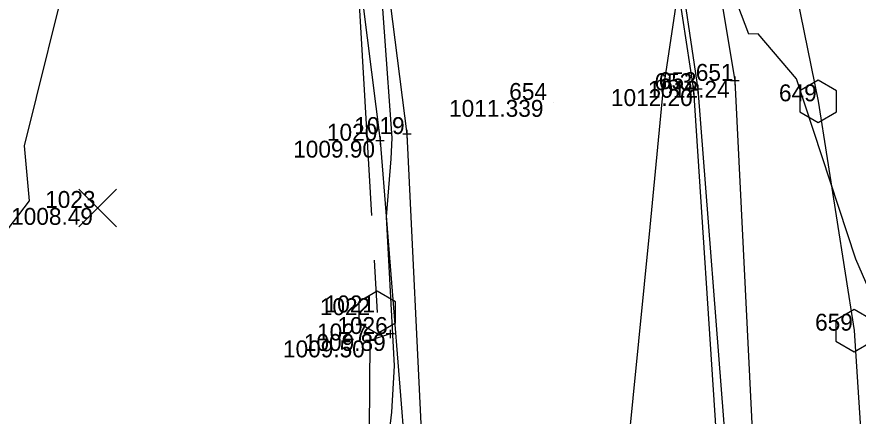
# Model space of a CAD drawing. Extents: x 2354693 to 2355622, y 637071 to 710080.
# Drawn here: x 2355324.2 to 2355383.9, y 709220.3 to 709248.7 of the extents above; entities that cross this region are included whole.
import ezdxf

# ---------------------------------------------------------------- set-up
doc = ezdxf.new("R2010")
doc.units = 0
for name, color, linetype in [('DT_X_Contour_Major', 7, 'Continuous'), ('DT_X_Contour_Minor', 7, 'Continuous'), ('PM_X_Surveyed_Line', 7, 'Continuous'), ('PV_X_EOP', 7, 'Continuous'), ('PV_X_Shoulder', 7, 'Continuous'), ('RD_X_Cells', 7, 'Continuous'), ('RD_X_GR_Lt', 7, 'Continuous'), ('RD_X_GR_Rt', 7, 'Continuous'), ('SV_X_Random_Point', 7, 'Continuous'), ('SV_X_Shot_Marker', 7, 'Continuous'), ('SV_X_Text_Elevation', 7, 'Continuous'), ('SV_X_Text_Name', 7, 'Continuous')]:
    doc.layers.add(name, color=color, linetype=linetype)

msp = doc.modelspace()

# ---------------------------------------------------------------- linework, layer by layer
at = {"layer": 'DT_X_Contour_Major'}
msp.add_lwpolyline([(2355382.151, 709274.282), (2355381.711, 709274.976), (2355380.703, 709275.914), (2355376.833, 709277.662), (2355375.801, 709278.001), (2355375.775, 709278.159), (2355374.352, 709276.373), (2355372.639, 709275.689), (2355367.547, 709272.887), (2355358.064, 709270.769), (2355356.817, 709270.34), (2355349.492, 709267.71), (2355349.176, 709262.706), (2355350.806, 709240.105), (2355350.736, 709238.617), (2355350.394, 709234.495), (2355350.966, 709223.924), (2355350.775, 709220.637), (2355349.098, 709206.498), (2355348.523, 709204.444)], dxfattribs=at)
msp.add_lwpolyline([(2355382.151, 709274.282), (2355381.711, 709274.976), (2355380.703, 709275.914), (2355376.833, 709277.662), (2355375.801, 709278.001), (2355375.775, 709278.159), (2355374.352, 709276.373), (2355372.639, 709275.689), (2355367.547, 709272.887), (2355358.064, 709270.769), (2355356.817, 709270.34), (2355349.492, 709267.71), (2355349.176, 709262.706), (2355350.806, 709240.105), (2355350.736, 709238.617), (2355350.394, 709234.495), (2355350.966, 709223.924), (2355350.775, 709220.637), (2355349.098, 709206.498), (2355348.523, 709204.444)], dxfattribs=at)
at = {"layer": 'DT_X_Contour_Minor'}
for points in [[(2355384.85, 709275.05), (2355383.235, 709274.854), (2355383.232, 709274.823), (2355376.649, 709277.797), (2355375.833, 709278.065), (2355375.782, 709278.367), (2355374.649, 709276.945), (2355370.84, 709275.422), (2355366.705, 709273.148), (2355359.006, 709271.428), (2355354.506, 709269.879), (2355346.203, 709266.898), (2355344.124, 709267.666), (2355343.708, 709266.508), (2355342.404, 709264.24), (2355341.712, 709262.62), (2355342.07, 709261.383), (2355340.341, 709258.201), (2355338.608, 709258.25), (2355328.095, 709253.197), (2355324.733, 709239.533), (2355325.082, 709235.631), (2355314.187, 709221.342)], [(2355384.85, 709275.05), (2355383.235, 709274.854), (2355383.232, 709274.823), (2355376.649, 709277.797), (2355375.833, 709278.065), (2355375.782, 709278.367), (2355374.649, 709276.945), (2355370.84, 709275.422), (2355366.705, 709273.148), (2355359.006, 709271.428), (2355354.506, 709269.879), (2355346.203, 709266.898), (2355344.124, 709267.666), (2355343.708, 709266.508), (2355342.404, 709264.24), (2355341.712, 709262.62), (2355342.07, 709261.383), (2355340.341, 709258.201), (2355338.608, 709258.25), (2355328.095, 709253.197), (2355324.733, 709239.533), (2355325.082, 709235.631), (2355314.187, 709221.342)], [(2355388.382, 709181.549), (2355387.248, 709201.609), (2355389.188, 709218.85), (2355383.697, 709231.486), (2355379.499, 709244.29), (2355376.776, 709247.498), (2355376.105, 709247.453), (2355373.371, 709254.729), (2355371.839, 709253.134), (2355371.28, 709251.764), (2355370.025, 709243.384), (2355369.092, 709233.774), (2355367.481, 709217.574), (2355362.053, 709192.157), (2355358.45, 709172.035)], [(2355388.382, 709181.549), (2355387.248, 709201.609), (2355389.188, 709218.85), (2355383.697, 709231.486), (2355379.499, 709244.29), (2355376.776, 709247.498), (2355376.105, 709247.453), (2355373.371, 709254.729), (2355371.839, 709253.134), (2355371.28, 709251.764), (2355370.025, 709243.384), (2355369.092, 709233.774), (2355367.481, 709217.574), (2355362.053, 709192.157), (2355358.45, 709172.035)]]:
    msp.add_lwpolyline(points, dxfattribs=at)
at = {"layer": 'PM_X_Surveyed_Line'}
msp.add_line((2355362.272, 709242.6), (2355362.272, 709242.6), dxfattribs=at)
for points in [[(2355180.148, 709561.237), (2355214.753, 709522.888), (2355249.307, 709484.271), (2355284.017, 709443.142), (2355315.552, 709399.77), (2355328.888, 709377.573), (2355342.967, 709349.789), (2355353.365, 709324.191), (2355361.351, 709299.648), (2355367.764, 709272.473), (2355372.191, 709243.487), (2355373.87, 709217.884), (2355371.213, 709164.414), (2355367.135, 709139.625), (2355360.061, 709111.877), (2355351.618, 709085.78), (2355342.505, 709062.338), (2355329.445, 709031.419), (2355320.624, 709012.583)], [(2355165.86, 709547.265), (2355199.549, 709510.037), (2355233.994, 709470.593), (2355267.54, 709430.367), (2355282.605, 709410.565), (2355297.684, 709388.575), (2355309.404, 709369.446), (2355323.831, 709342.426), (2355334.056, 709318.38), (2355342.286, 709293.43), (2355348.466, 709267.168), (2355351.872, 709240.375), (2355352.964, 709217.38), (2355352.456, 709191.088), (2355350.186, 709167.624), (2355345.964, 709144.005), (2355339.847, 709117.861), (2355332.105, 709093.739), (2355322.597, 709069.077), (2355314.612, 709050.664), (2355300.362, 709021.696)]]:
    msp.add_lwpolyline(points, dxfattribs=at)
at = {"layer": 'PV_X_EOP'}
for points in [[(2355180.814, 709561.741), (2355215.64, 709523.556), (2355249.922, 709484.356), (2355284.407, 709443.36), (2355315.939, 709399.966), (2355329.751, 709378.355), (2355343.524, 709350.098), (2355349.219, 709351.4), (2355359.304, 709326.795), (2355367.588, 709301.754), (2355374.108, 709275.907), (2355368.17, 709272.694), (2355372.498, 709243.563), (2355374.502, 709217.665), (2355371.414, 709164.432), (2355367.842, 709139.325), (2355361.02, 709111.642), (2355352.388, 709085.56), (2355343.445, 709061.967), (2355330.49, 709031.083), (2355321.141, 709011.801)], [(2355165.324, 709546.951), (2355198.995, 709509.502), (2355233.405, 709470.111), (2355266.728, 709429.76), (2355281.934, 709410.085), (2355297.047, 709388.167), (2355308.637, 709369.042), (2355321.448, 709342.933), (2355321.339, 709342.62), (2355331.824, 709317.677), (2355340.036, 709292.971), (2355346.601, 709266.722), (2355349.963, 709239.902), (2355351.76, 709217.379), (2355351.561, 709190.756), (2355349.316, 709167.656), (2355345.615, 709144.125), (2355339.519, 709118.013), (2355331.95, 709093.674), (2355322.309, 709069.242), (2355314.268, 709051.111), (2355300.286, 709022.246)]]:
    msp.add_lwpolyline(points, dxfattribs=at)
at = {"layer": 'PV_X_Shoulder'}
for points in [[(2355370.563, 709271.651), (2355375.125, 709244.152), (2355376.457, 709217.439), (2355373.313, 709164.025), (2355369.833, 709138.826), (2355363.46, 709110.733), (2355354.734, 709084.843), (2355345.666, 709061.243), (2355332.683, 709029.848), (2355323.397, 709011.312)], [(2355350.692, 709226.183), (2355349.237, 709225.724), (2355348.983, 709190.632), (2355347.11, 709167.944), (2355343.481, 709144.038), (2355337.288, 709118.882), (2355329.716, 709094.535), (2355320.778, 709071.235), (2355312.538, 709052.234), (2355298.997, 709024.071)]]:
    msp.add_lwpolyline(points, dxfattribs=at)
at = {"layer": 'RD_X_Cells'}
for points in [[(2355379.732, 709241.95), (2355381.031, 709241.2), (2355382.329, 709241.95), (2355382.329, 709243.45), (2355381.031, 709244.2), (2355379.732, 709243.45), (2355379.732, 709241.95)], [(2355348.463, 709226.967), (2355349.761, 709226.217), (2355351.06, 709226.967), (2355351.06, 709228.467), (2355349.761, 709229.217), (2355348.463, 709228.467), (2355348.463, 709226.967)], [(2355382.294, 709225.669), (2355383.592, 709224.919), (2355384.89, 709225.669), (2355384.89, 709227.169), (2355383.592, 709227.919), (2355382.294, 709227.169), (2355382.294, 709225.669)]]:
    msp.add_lwpolyline(points, dxfattribs=at)
at = {"layer": 'RD_X_GR_Lt'}
msp.add_lwpolyline([(2355373.985, 709277.316), (2355381.031, 709242.7), (2355383.592, 709226.419), (2355385.198, 709201.576), (2355387.106, 709175.345)], dxfattribs=at)
at = {"layer": 'RD_X_GR_Rt'}
for points in [[(2355346.032, 709267.427), (2355348.411, 709250.816), (2355349.36, 709234.583)], [(2355349.545, 709231.424), (2355349.761, 709227.717)]]:
    msp.add_lwpolyline(points, dxfattribs=at)
at = {"layer": 'SV_X_Random_Point'}
for p, q in [((2355328.597, 709233.796), (2355331.264, 709236.466)), ((2355328.597, 709236.466), (2355331.264, 709233.796))]:
    msp.add_line(p, q, dxfattribs=at)
at = {"layer": 'SV_X_Shot_Marker'}
for p, q in [((2355375.425, 709244.152), (2355374.825, 709244.152)), ((2355375.125, 709244.452), (2355375.125, 709243.852)), ((2355372.491, 709243.487), (2355371.891, 709243.487)), ((2355372.191, 709243.787), (2355372.191, 709243.187)), ((2355372.798, 709243.563), (2355372.198, 709243.563)), ((2355372.498, 709243.863), (2355372.498, 709243.263)), ((2355351.872, 709240.675), (2355351.872, 709240.075)), ((2355350.263, 709239.902), (2355349.663, 709239.902)), ((2355349.963, 709240.202), (2355349.963, 709239.602)), ((2355352.172, 709240.375), (2355351.572, 709240.375)), ((2355350.992, 709226.183), (2355350.392, 709226.183)), ((2355350.692, 709226.483), (2355350.692, 709225.883)), ((2355349.537, 709225.724), (2355348.937, 709225.724)), ((2355349.237, 709226.024), (2355349.237, 709225.424))]:
    msp.add_line(p, q, dxfattribs=at)

# ---------------------------------------------------------------- texts
at = {"layer": 'SV_X_Text_Elevation'}
for s, p in [('1012.24', (2355368.955, 709242.952)), ('1012.20', (2355366.339, 709242.363)), ('1011.339', (2355354.859, 709241.598)), ('1009.90', (2355343.804, 709238.702)), ('1008.49', (2355323.802, 709233.931)), ('1009.89', (2355344.564, 709224.983)), ('1009.50', (2355343.079, 709224.524))]:
    msp.add_text(s, height=1.2, dxfattribs=at).set_placement(p)
at = {"layer": 'SV_X_Text_Name'}
for s, p in [('651', (2355372.354, 709244.152)), ('653', (2355369.432, 709243.487)), ('652', (2355369.73, 709243.563)), ('654', (2355359.126, 709242.798)), ('649', (2355378.253, 709242.7)), ('1020', (2355346.197, 709239.902)), ('1019', (2355348.137, 709240.375)), ('1023', (2355326.215, 709235.132)), ('1022', (2355345.694, 709227.521)), ('1021', (2355346.033, 709227.717)), ('1026', (2355346.936, 709226.183)), ('659', (2355380.815, 709226.419)), ('1027', (2355345.493, 709225.724))]:
    msp.add_text(s, height=1.2, dxfattribs=at).set_placement(p)

doc.saveas('drawing.dxf')
